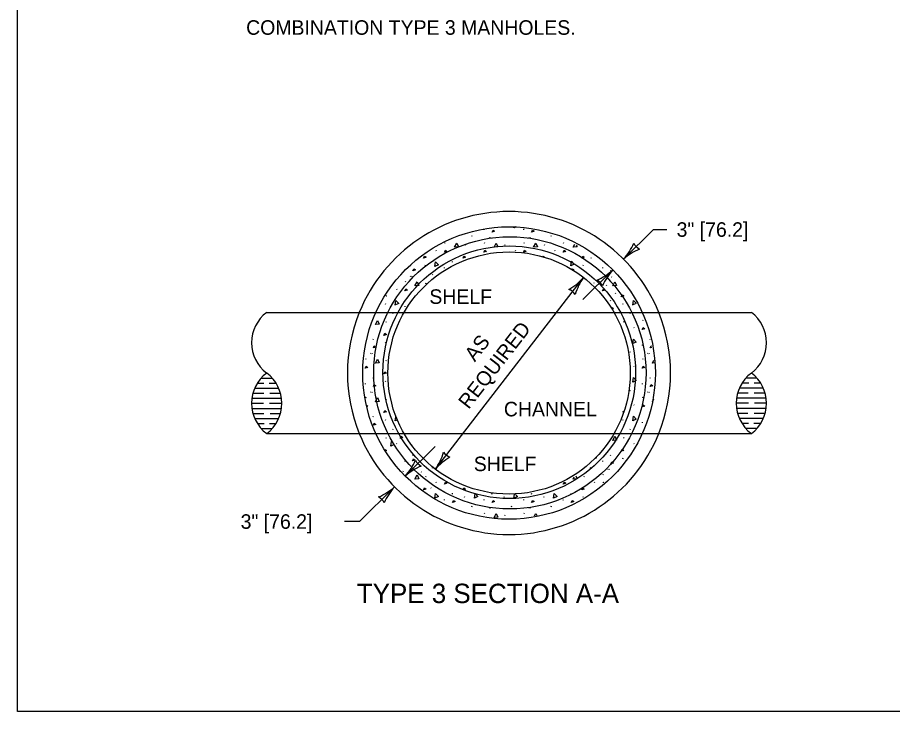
# Model space of a CAD drawing. Extents: x 49991.4 to 50028.3, y 49987.6 to 50011.4.
# Drawn here: x 49999.384 to 50002.994, y 49987.799 to 49990.664 of the extents above; entities that cross this region are included whole.
import ezdxf

# ---------------------------------------------------------------- set-up
doc = ezdxf.new("R2010")
doc.units = 0
for name, color, linetype in [('Level 1', 7, 'Continuous'), ('Level 2', 7, 'Continuous'), ('Level 3', 7, 'Continuous'), ('Level 4', 7, 'Continuous')]:
    doc.layers.add(name, color=color, linetype=linetype)

msp = doc.modelspace()

# ---------------------------------------------------------------- linework, layer by layer
at = {"layer": 'Level 1'}
for p, q in [((50001.2588, 49989.7606), (50001.2602, 49989.7636)), ((50001.3077, 49989.7909), (50001.308, 49989.7879)), ((50001.3304, 49989.7567), (50001.3318, 49989.7547)), ((50001.3355, 49989.7559), (50001.3368, 49989.7539)), ((50001.471, 49989.7909), (50001.4713, 49989.7879)), ((50001.4937, 49989.7567), (50001.495, 49989.7547)), ((50001.4988, 49989.7559), (50001.5001, 49989.7539)), ((50001.5854, 49989.7606), (50001.5867, 49989.7636)), ((50001.1475, 49989.732), (50001.1488, 49989.735)), ((50001.2319, 49989.7243), (50001.2332, 49989.7273)), ((50001.3108, 49989.732), (50001.3121, 49989.735)), ((50001.3951, 49989.7243), (50001.3961, 49989.7265)), ((50001.474, 49989.732), (50001.4754, 49989.735)), ((50001.5584, 49989.7243), (50001.5597, 49989.7273)), ((50001.6373, 49989.732), (50001.6386, 49989.735)), ((50001.1102, 49989.7031), (50001.1116, 49989.7011)), ((50001.2735, 49989.7031), (50001.2748, 49989.7011)), ((50001.4368, 49989.7031), (50001.4381, 49989.7011)), ((50001.6, 49989.7031), (50001.6014, 49989.7011)), ((50001.1779, 49989.6534), (50001.1792, 49989.6564)), ((50001.6677, 49989.6534), (50001.669, 49989.6564)), ((50001.7505, 49989.6697), (50001.7518, 49989.6727)), ((50001.0653, 49989.6398), (50001.0666, 49989.6428)), ((50001.1444, 49989.6314), (50001.1448, 49989.6284)), ((50001.7183, 49989.6398), (50001.7197, 49989.6428)), ((50001.7975, 49989.6314), (50001.7978, 49989.6284)), ((50000.9842, 49989.5725), (50000.9856, 49989.5755)), ((50001.0039, 49989.5973), (50001.0052, 49989.5953)), ((50001.009, 49989.5965), (50001.0103, 49989.5945)), ((50001.0956, 49989.6011), (50001.0969, 49989.6041)), ((50001.835, 49989.5935), (50001.8364, 49989.5915)), ((50000.947, 49989.5436), (50000.9483, 49989.5416)), ((50001.0686, 49989.5649), (50001.0699, 49989.5679)), ((50001.7628, 49989.5667), (50001.7637, 49989.5687)), ((50001.8146, 49989.5574), (50001.8159, 49989.5604)), ((50001.8501, 49989.5269), (50001.8514, 49989.5249)), ((50000.902, 49989.4803), (50000.9034, 49989.4833)), ((50000.9812, 49989.4719), (50000.9815, 49989.4689)), ((50001.831, 49989.494), (50001.8323, 49989.497)), ((50001.8816, 49989.4803), (50001.8829, 49989.4833)), ((50000.4118, 49989.4461), (50000.8623, 49989.4461)), ((50000.9323, 49989.4417), (50000.9336, 49989.4447)), ((50000.9788, 49989.4461), (50001.8449, 49989.4461)), ((50001.9119, 49989.4417), (50001.9132, 49989.4447)), ((50001.9613, 49989.4461), (50002.4118, 49989.4461)), ((50000.9054, 49989.4055), (50000.9067, 49989.4085)), ((50001.8849, 49989.4055), (50001.8863, 49989.4085)), ((50001.9638, 49989.4131), (50001.9652, 49989.4161)), ((50000.947, 49989.3841), (50000.9483, 49989.3821)), ((50001.9266, 49989.3841), (50001.9279, 49989.3821)), ((50000.8514, 49989.3345), (50000.8527, 49989.3375)), ((50000.902, 49989.3209), (50000.9034, 49989.3239)), ((50001.9942, 49989.3345), (50001.9948, 49989.3357)), ((50001.9608, 49989.3125), (50001.9611, 49989.3095)), ((50000.821, 49989.2537), (50000.8223, 49989.2567)), ((50000.8406, 49989.2783), (50000.842, 49989.2763)), ((50000.8457, 49989.2776), (50000.847, 49989.2756)), ((50001.9119, 49989.2822), (50001.9132, 49989.2852)), ((50001.9638, 49989.2537), (50001.9652, 49989.2567)), ((50001.9835, 49989.2783), (50001.9848, 49989.2763)), ((50001.9886, 49989.2776), (50001.9899, 49989.2756)), ((50000.9054, 49989.246), (50000.9067, 49989.249)), ((50001.9266, 49989.2247), (50001.9279, 49989.2227)), ((50000.8514, 49989.1751), (50000.8527, 49989.1781)), ((50001.9942, 49989.1751), (50001.9956, 49989.1781)), ((50000.3734, 49989.1545), (50000.3995, 49989.1545)), ((50000.3891, 49989.1753), (50000.4345, 49989.1753)), ((50000.4219, 49989.1545), (50000.4502, 49989.1545)), ((50000.8179, 49989.1531), (50000.8182, 49989.1501)), ((50000.902, 49989.1614), (50000.9034, 49989.1644)), ((50001.9608, 49989.1531), (50001.9611, 49989.1501)), ((50002.4017, 49989.1545), (50002.3734, 49989.1545)), ((50002.4346, 49989.1753), (50002.3891, 49989.1753)), ((50002.4502, 49989.1545), (50002.4241, 49989.1545)), ((50000.355, 49989.1128), (50000.4006, 49989.1128)), ((50000.3624, 49989.1336), (50000.4612, 49989.1336)), ((50000.4252, 49989.1128), (50000.4686, 49989.1128)), ((50000.8406, 49989.1189), (50000.842, 49989.1169)), ((50000.8457, 49989.1181), (50000.847, 49989.1161)), ((50001.9119, 49989.1228), (50001.9132, 49989.1258)), ((50001.9835, 49989.1189), (50001.9848, 49989.1169)), ((50001.9886, 49989.1181), (50001.9899, 49989.1161)), ((50002.3985, 49989.1128), (50002.355, 49989.1128)), ((50002.4613, 49989.1336), (50002.3624, 49989.1336)), ((50002.4687, 49989.1128), (50002.423, 49989.1128)), ((50000.3493, 49989.0711), (50000.3984, 49989.0711)), ((50000.3507, 49989.0919), (50000.4729, 49989.0919)), ((50000.423, 49989.0711), (50000.4743, 49989.0711)), ((50000.821, 49989.0942), (50000.8223, 49989.0972)), ((50000.9054, 49989.0865), (50000.9067, 49989.0895)), ((50001.9638, 49989.0942), (50001.9652, 49989.0972)), ((50002.4006, 49989.0711), (50002.3494, 49989.0711)), ((50002.473, 49989.0919), (50002.3508, 49989.0919)), ((50002.4744, 49989.0711), (50002.4252, 49989.0711)), ((50000.3507, 49989.0503), (50000.4729, 49989.0503)), ((50001.9266, 49989.0652), (50001.9279, 49989.0632)), ((50002.473, 49989.0503), (50002.3508, 49989.0503)), ((50000.355, 49989.0295), (50000.3995, 49989.0295)), ((50000.3624, 49989.0086), (50000.4612, 49989.0086)), ((50000.4262, 49989.0295), (50000.4686, 49989.0295)), ((50000.8514, 49989.0156), (50000.8527, 49989.0186)), ((50000.902, 49989.0019), (50000.9034, 49989.0049)), ((50001.8816, 49989.0019), (50001.8829, 49989.0049)), ((50002.3974, 49989.0295), (50002.355, 49989.0295)), ((50002.4613, 49989.0086), (50002.3624, 49989.0086)), ((50002.4687, 49989.0295), (50002.4241, 49989.0295)), ((50000.3734, 49988.9878), (50000.4016, 49988.9878)), ((50000.3891, 49988.9669), (50000.4345, 49988.9669)), ((50000.424, 49988.9878), (50000.4502, 49988.9878)), ((50000.9323, 49988.9633), (50000.9336, 49988.9663)), ((50001.9119, 49988.9633), (50001.9132, 49988.9663)), ((50001.9608, 49988.9936), (50001.9611, 49988.9906)), ((50002.3996, 49988.9878), (50002.3734, 49988.9878)), ((50002.4346, 49988.9669), (50002.3891, 49988.9669)), ((50002.4502, 49988.9878), (50002.422, 49988.9878)), ((50000.4118, 49988.9461), (50000.8624, 49988.9461)), ((50000.9054, 49988.9271), (50000.9067, 49988.9301)), ((50000.9789, 49988.9461), (50001.8448, 49988.9461)), ((50001.8849, 49988.9271), (50001.8863, 49988.9301)), ((50001.9613, 49988.9461), (50002.4118, 49988.9461)), ((50000.947, 49988.9058), (50000.9483, 49988.9038)), ((50001.0092, 49988.8999), (50001.0101, 49988.8986)), ((50001.9266, 49988.9058), (50001.9279, 49988.9038)), ((50001.0146, 49988.8561), (50001.016, 49988.8591)), ((50001.831, 49988.8561), (50001.8323, 49988.8591)), ((50000.9812, 49988.8341), (50000.9815, 49988.8311)), ((50001.7975, 49988.8341), (50001.7978, 49988.8311)), ((50001.8816, 49988.8425), (50001.8829, 49988.8455)), ((50000.9751, 49988.7898), (50000.9765, 49988.7928)), ((50001.0492, 49988.7883), (50001.0505, 49988.7863)), ((50001.0956, 49988.8039), (50001.0962, 49988.8052)), ((50001.7486, 49988.8039), (50001.75, 49988.8069)), ((50001.8202, 49988.8), (50001.8216, 49988.798)), ((50001.8253, 49988.7992), (50001.8266, 49988.7972)), ((50001.0686, 49988.7676), (50001.0699, 49988.7706)), ((50001.1102, 49988.7463), (50001.1116, 49988.7443)), ((50001.7217, 49988.7676), (50001.723, 49988.7706)), ((50001.7633, 49988.7463), (50001.7646, 49988.7443)), ((50001.8006, 49988.7753), (50001.8019, 49988.7783)), ((50001.0892, 49988.7223), (50001.0905, 49988.7203)), ((50001.1444, 49988.6747), (50001.1448, 49988.6717)), ((50001.1779, 49988.6967), (50001.1792, 49988.6997)), ((50001.2286, 49988.6831), (50001.2299, 49988.686)), ((50001.3077, 49988.6747), (50001.308, 49988.6717)), ((50001.3412, 49988.6967), (50001.3425, 49988.6997)), ((50001.3918, 49988.6831), (50001.3932, 49988.686)), ((50001.471, 49988.6747), (50001.4713, 49988.6717)), ((50001.5044, 49988.6967), (50001.5058, 49988.6997)), ((50001.5551, 49988.6831), (50001.5564, 49988.686)), ((50001.6342, 49988.6747), (50001.6346, 49988.6717)), ((50001.6677, 49988.6967), (50001.669, 49988.6997)), ((50001.7183, 49988.6831), (50001.7197, 49988.686)), ((50001.2588, 49988.6444), (50001.2602, 49988.6474)), ((50001.3304, 49988.6405), (50001.3318, 49988.6385)), ((50001.3355, 49988.6397), (50001.3368, 49988.6377)), ((50001.4221, 49988.6444), (50001.4234, 49988.6474)), ((50001.4937, 49988.6405), (50001.495, 49988.6385)), ((50001.4988, 49988.6397), (50001.5001, 49988.6377)), ((50001.5854, 49988.6444), (50001.5867, 49988.6474)), ((50001.3108, 49988.6158), (50001.3121, 49988.6188)), ((50001.3951, 49988.6082), (50001.3965, 49988.6112)), ((50001.474, 49988.6158), (50001.4754, 49988.6188))]:
    msp.add_line(p, q, dxfattribs=at)
msp.add_lwpolyline([(49999.3835, 49998.9992), (50016.7501, 49998.9992), (50016.7501, 49987.7988), (49999.3835, 49987.7988)], close=True, dxfattribs=at)
for points in [[(50001.4323, 49989.7958), (50001.4328, 49989.7994)], [(50001.4402, 49989.7994), (50001.4326, 49989.7959)], [(50001.3418, 49989.7779), (50001.3458, 49989.7863), (50001.3525, 49989.7813), (50001.3418, 49989.7779)], [(50001.5051, 49989.7779), (50001.5091, 49989.7863), (50001.5158, 49989.7813), (50001.5051, 49989.7779)], [(50001.1869, 49989.7154), (50001.1959, 49989.7323), (50001.2029, 49989.7167), (50001.1872, 49989.7154)], [(50001.3502, 49989.7154), (50001.3592, 49989.7323), (50001.3662, 49989.7167), (50001.3505, 49989.7154)], [(50001.5134, 49989.7154), (50001.5224, 49989.7323), (50001.5294, 49989.7167), (50001.5138, 49989.7154)], [(50001.6767, 49989.7154), (50001.6832, 49989.7276)], [(50001.6893, 49989.7243), (50001.6927, 49989.7167), (50001.677, 49989.7154)], [(50001.1452, 49989.6944), (50001.1492, 49989.7027), (50001.1558, 49989.6977), (50001.1452, 49989.6944)], [(50001.3084, 49989.6944), (50001.3124, 49989.7027), (50001.3191, 49989.6977), (50001.3084, 49989.6944)], [(50001.4717, 49989.6944), (50001.4757, 49989.7027), (50001.4824, 49989.6977), (50001.4717, 49989.6944)], [(50001.635, 49989.6944), (50001.639, 49989.7027), (50001.6456, 49989.6977), (50001.635, 49989.6944)], [(50001.0587, 49989.6706), (50001.0627, 49989.6789), (50001.0693, 49989.6739), (50001.0587, 49989.6706)], [(50001.1058, 49989.6363), (50001.1084, 49989.6553), (50001.1204, 49989.6431), (50001.1061, 49989.6365)], [(50001.222, 49989.6706), (50001.226, 49989.6789), (50001.2326, 49989.6739), (50001.222, 49989.6706)], [(50001.5517, 49989.6773), (50001.5525, 49989.6789), (50001.558, 49989.6747)], [(50001.6663, 49989.6388), (50001.669, 49989.6578), (50001.6809, 49989.6455), (50001.6666, 49989.6389)], [(50001.7118, 49989.6706), (50001.7158, 49989.6789), (50001.7224, 49989.6739), (50001.7118, 49989.6706)], [(50001.0153, 49989.6185), (50001.0193, 49989.6268), (50001.026, 49989.6218), (50001.0153, 49989.6185)], [(50001.6714, 49989.6247), (50001.6724, 49989.6268), (50001.679, 49989.6218), (50001.6763, 49989.6209)], [(50001.8316, 49989.6185), (50001.8327, 49989.6207)], [(50001.834, 49989.6192), (50001.8316, 49989.6185)], [(50000.9819, 49989.5349), (50000.9859, 49989.5433), (50000.9926, 49989.5383), (50000.9819, 49989.5349)], [(50001.0236, 49989.5559), (50001.0326, 49989.5729), (50001.0396, 49989.5573), (50001.024, 49989.5559)], [(50001.7982, 49989.5349), (50001.8022, 49989.5433), (50001.8089, 49989.5383), (50001.7982, 49989.5349)], [(50001.84, 49989.5559), (50001.849, 49989.5729), (50001.856, 49989.5573), (50001.8403, 49989.5559)], [(50000.9048, 49989.5154), (50000.9061, 49989.5145), (50000.9039, 49989.5138)], [(50001.875, 49989.5111), (50001.879, 49989.5195), (50001.8857, 49989.5145), (50001.875, 49989.5111)], [(50000.9425, 49989.4769), (50000.9452, 49989.4959), (50000.9571, 49989.4836), (50000.9428, 49989.477)], [(50001.8342, 49989.4638), (50001.8356, 49989.4673), (50001.8423, 49989.4623), (50001.8363, 49989.4605)], [(50001.9221, 49989.4769), (50001.9248, 49989.4959), (50001.9361, 49989.4842)], [(50001.9364, 49989.4835), (50001.9224, 49989.477)], [(50000.8604, 49989.3965), (50000.8694, 49989.4134), (50000.8764, 49989.3978), (50000.8607, 49989.3965)], [(50000.8954, 49989.3517), (50000.8994, 49989.36), (50000.9061, 49989.355), (50000.8954, 49989.3517)], [(50001.9615, 49989.3755), (50001.9655, 49989.3838), (50001.9722, 49989.3788), (50001.9615, 49989.3755)], [(50001.9221, 49989.3174), (50001.9248, 49989.3365), (50001.9367, 49989.3241), (50001.9224, 49989.3175)], [(50000.852, 49989.2995), (50000.856, 49989.3079), (50000.8627, 49989.3029), (50000.852, 49989.2995)], [(50001.9949, 49989.2995), (50001.9989, 49989.3079), (50001.9998, 49989.3073)], [(50002.0008, 49989.3014), (50001.9949, 49989.2995)], [(50000.8604, 49989.237), (50000.8694, 49989.254), (50000.8764, 49989.2383), (50000.8607, 49989.237)], [(50000.8187, 49989.216), (50000.8226, 49989.2243), (50000.8293, 49989.2193), (50000.8187, 49989.216)], [(50001.9615, 49989.216), (50001.9655, 49989.2243), (50001.9722, 49989.2193), (50001.9615, 49989.216)], [(50002.0032, 49989.237), (50002.0099, 49989.2495)], [(50002.0119, 49989.2377), (50002.0036, 49989.237)], [(50000.8954, 49989.1922), (50000.8994, 49989.2005), (50000.9061, 49989.1955), (50000.8954, 49989.1922)], [(50000.852, 49989.1401), (50000.856, 49989.1484), (50000.8627, 49989.1434), (50000.852, 49989.1401)], [(50001.9221, 49989.1579), (50001.9248, 49989.177), (50001.9367, 49989.1647), (50001.9224, 49989.1581)], [(50001.9949, 49989.1401), (50001.9989, 49989.1484), (50002.0056, 49989.1434), (50001.9949, 49989.1401)], [(50000.8604, 49989.0775), (50000.8694, 49989.0945), (50000.8764, 49989.0789), (50000.8607, 49989.0775)], [(50002.0032, 49989.0775), (50002.0098, 49989.0899)], [(50002.0054, 49989.0777), (50002.0036, 49989.0775)], [(50000.8227, 49989.0649), (50000.8293, 49989.0599), (50000.8239, 49989.0582)], [(50000.8954, 49989.0327), (50000.8994, 49989.0411), (50000.9061, 49989.0361), (50000.8954, 49989.0327)], [(50001.8818, 49989.039), (50001.8857, 49989.0361), (50001.88, 49989.0343)], [(50001.9615, 49989.0566), (50001.9655, 49989.0649), (50001.9722, 49989.0599), (50001.9615, 49989.0566)], [(50000.9425, 49988.9985), (50000.9449, 49989.0159)], [(50000.9494, 49989.0017), (50000.9428, 49988.9986)], [(50001.9221, 49988.9985), (50001.9248, 49989.0175), (50001.9367, 49989.0052), (50001.9224, 49988.9986)], [(50000.8521, 49988.9808), (50000.856, 49988.989), (50000.8627, 49988.984), (50000.8522, 49988.9807)], [(50000.9624, 49988.9268), (50000.9664, 49988.9351), (50000.9731, 49988.9301), (50000.9624, 49988.9268)], [(50001.84, 49988.9181), (50001.849, 49988.9351), (50001.856, 49988.9194), (50001.8403, 49988.9181)], [(50000.9236, 49988.8943), (50000.9263, 49988.9133), (50000.9382, 49988.901), (50000.924, 49988.8944)], [(50000.9002, 49988.8811), (50000.9061, 49988.8766), (50000.9029, 49988.8756)], [(50001.875, 49988.8733), (50001.879, 49988.8816), (50001.8857, 49988.8766), (50001.875, 49988.8733)], [(50001.0135, 49988.8333), (50001.0175, 49988.8416), (50001.0242, 49988.8366), (50001.0135, 49988.8333)], [(50001.7713, 49988.848), (50001.7734, 49988.8458), (50001.7672, 49988.8429)], [(50001.8316, 49988.8212), (50001.8356, 49988.8295), (50001.8423, 49988.8245), (50001.8316, 49988.8212)], [(50001.0236, 49988.7586), (50001.0326, 49988.7756), (50001.0396, 49988.76), (50001.024, 49988.7586)], [(50001.1452, 49988.7377), (50001.1492, 49988.746), (50001.1558, 49988.741), (50001.1452, 49988.7377)], [(50001.635, 49988.7377), (50001.639, 49988.746), (50001.6456, 49988.741), (50001.635, 49988.7377)], [(50001.6767, 49988.7586), (50001.6811, 49988.767)], [(50001.6876, 49988.7715), (50001.6927, 49988.76), (50001.677, 49988.7586)], [(50001.801, 49988.7433), (50001.8022, 49988.746), (50001.8032, 49988.7453)], [(50001.0587, 49988.7139), (50001.0627, 49988.7222), (50001.0693, 49988.7172), (50001.0587, 49988.7139)], [(50001.222, 49988.7139), (50001.226, 49988.7222), (50001.2326, 49988.7172), (50001.222, 49988.7139)], [(50001.7118, 49988.7139), (50001.7158, 49988.7222), (50001.7224, 49988.7172), (50001.7118, 49988.7139)], [(50001.1058, 49988.6796), (50001.1084, 49988.6986), (50001.1204, 49988.6863), (50001.1061, 49988.6797)], [(50001.269, 49988.6796), (50001.2717, 49988.6986), (50001.2836, 49988.6863), (50001.2694, 49988.6797)], [(50001.4323, 49988.6796), (50001.4344, 49988.6947)], [(50001.4382, 49988.6953), (50001.4469, 49988.6863), (50001.4326, 49988.6797)], [(50001.5956, 49988.6796), (50001.5982, 49988.6986), (50001.6102, 49988.6863), (50001.5959, 49988.6797)], [(50001.1786, 49988.6617), (50001.1826, 49988.6701), (50001.1892, 49988.6651), (50001.1786, 49988.6617)], [(50001.3418, 49988.6617), (50001.3458, 49988.6701), (50001.3525, 49988.6651), (50001.3418, 49988.6617)], [(50001.5051, 49988.6617), (50001.5091, 49988.6701), (50001.5158, 49988.6651), (50001.5051, 49988.6617)], [(50001.6684, 49988.6617), (50001.6724, 49988.6701), (50001.679, 49988.6651), (50001.6684, 49988.6617)], [(50001.3504, 49988.5995), (50001.3592, 49988.6161), (50001.3662, 49988.6005), (50001.3537, 49988.5995)], [(50001.5171, 49988.6061), (50001.5224, 49988.6161), (50001.526, 49988.6081)], [(50001.3536, 49988.5995), (50001.3535, 49988.5995)], [(50001.3535, 49988.5995), (50001.3535, 49988.5995)], [(50001.3537, 49988.5995), (50001.3536, 49988.5995)], [(50001.3536, 49988.5995), (50001.3536, 49988.5995)]]:
    msp.add_lwpolyline(points, dxfattribs=at)
for centre, radius in [((50001.4119, 49989.1962), 0.6037), ((50001.4152, 49989.1968), 0.5619), ((50001.4128, 49989.1993), 0.5213), ((50001.4119, 49989.1962), 0.5)]:
    msp.add_circle(centre, radius, dxfattribs=at)
for centre, radius, start, end in [((50001.4118, 49989.1964), 0.6664, 22.0028, 157.9972), ((50000.5056, 49989.3212), 0.1563, 126.8699, 233.1301), ((50002.3181, 49989.3212), 0.1563, 306.8699, 53.1301), ((50000.5056, 49989.0712), 0.1563, 126.8699, 233.1301), ((50000.3181, 49989.0712), 0.1563, 306.8699, 53.1301), ((50002.5056, 49989.0712), 0.1563, 126.8699, 233.1301), ((50002.3181, 49989.0712), 0.1563, 306.8699, 53.1301), ((50001.4118, 49989.196), 0.6665, 202.0199, 337.9801)]:
    msp.add_arc(centre, radius, start, end, dxfattribs=at)
at = {"layer": 'Level 3'}
for p, q in [((50001.8846, 49989.6661), (50002.0075, 49989.7885)), ((50002.0075, 49989.7885), (50002.0634, 49989.7885)), ((50001.717, 49989.4996), (50001.84, 49989.6218)), ((50001.1079, 49988.7992), (50001.7189, 49989.5908)), ((50000.9837, 49988.7705), (50001.1068, 49988.8927)), ((50000.9837, 49988.7705), (50001.0453, 49988.8318)), ((50000.7951, 49988.583), (50000.9369, 49988.7239)), ((50000.7951, 49988.583), (50000.7329, 49988.583))]:
    msp.add_line(p, q, dxfattribs=at)
for centre, radius, start, end in [((50001.7123, 49989.823), 0.233, 317.6876, 336.9375), ((50001.9755, 49989.7566), 0.0548, 206.9991, 242.7215), ((50002.0348, 49989.5022), 0.2223, 112.3163, 132.4998), ((50001.6899, 49989.7858), 0.2223, 292.2764, 312.4599), ((50002.0122, 49989.4648), 0.233, 137.6477, 156.8976), ((50001.5496, 49989.7348), 0.2223, 299.4184, 319.6019), ((50001.9093, 49989.4564), 0.233, 144.7897, 164.0396), ((50001.7491, 49989.5314), 0.0548, 26.9592, 62.6816), ((50001.6399, 49989.4898), 0.0548, 34.1012, 69.8236), ((50000.9175, 49988.9334), 0.233, 324.806, 344.0558), ((50001.1869, 49988.9002), 0.0548, 214.1175, 249.8398), ((50000.8114, 49988.9274), 0.233, 317.6875, 336.9373), ((50001.0746, 49988.861), 0.0548, 206.999, 242.7213), ((50001.2773, 49988.6551), 0.2223, 119.4347, 139.6182), ((50001.1339, 49988.6066), 0.2223, 112.3162, 132.4997), ((50000.7891, 49988.8902), 0.2223, 292.2764, 312.4599), ((50001.1113, 49988.5692), 0.233, 137.6477, 156.8976), ((50000.8482, 49988.6358), 0.0548, 26.9592, 62.6816)]:
    msp.add_arc(centre, radius, start, end, dxfattribs=at)
at = {"layer": 'Level 4'}
for p, q in [((50000.8623, 49989.4461), (50000.9788, 49989.4461)), ((50001.8449, 49989.4461), (50001.9613, 49989.4461)), ((50000.8624, 49988.9461), (50000.9789, 49988.9461)), ((50001.8448, 49988.9461), (50001.9613, 49988.9461))]:
    msp.add_line(p, q, dxfattribs=at)
for start, end in [(157.9719, 202.0281), (337.9719, 22.0281)]:
    msp.add_arc((50001.4118, 49989.1961), 0.6666, start, end, dxfattribs=at)

# ---------------------------------------------------------------- texts
at = {"layer": 'Level 2'}
for s, height, p in [('COMBINATION TYPE 3 MANHOLES.', 0.06, (50000.327, 49990.5925)), ('3" [76.2]', 0.06, (50002.1034, 49989.7585)), ('SHELF', 0.06, (50001.0831, 49989.4816)), ('CHANNEL', 0.06, (50001.3907, 49989.0172)), ('SHELF', 0.06, (50001.2664, 49988.7911)), ('3" [76.2]', 0.06, (50000.3043, 49988.553)), ('TYPE 3 SECTION A-A', 0.08, (50000.7839, 49988.2464))]:
    msp.add_text(s, height=height, dxfattribs=at).set_placement(p)
for s, p in [('REQUIRED', (50001.2451, 49989.0435)), ('AS', (50001.2708, 49989.2396))]:
    msp.add_text(s, height=0.06, rotation=52.166, dxfattribs=at).set_placement(p)

doc.saveas('drawing.dxf')
